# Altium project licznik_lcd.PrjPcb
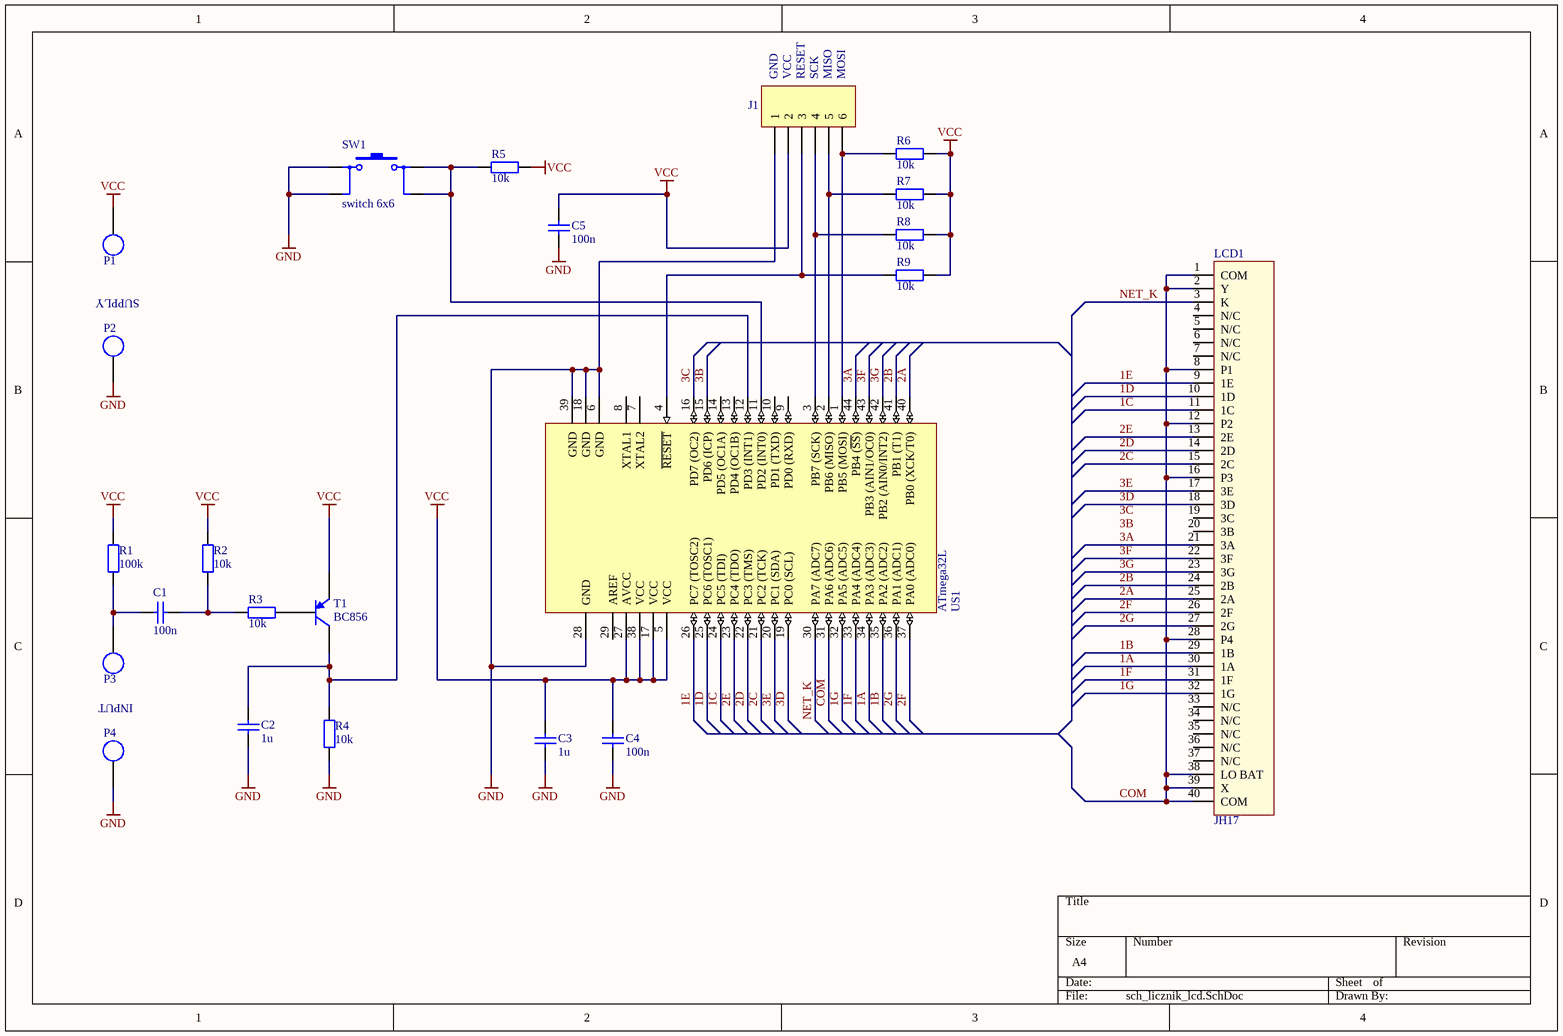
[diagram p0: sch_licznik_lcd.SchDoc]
1 sheet, 23 parts. Net scope: global (net labels, ports and power ports of the same name join across sheets).
Board file: pcb_licznik_lcd.PcbDoc

## Sheet sch_licznik_lcd.SchDoc
size A4

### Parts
C1  100n  [MELF-1206]
C2  1u  [MELF-1206]
C3  1u  [MELF-1206]
C4  100n  [MELF-1206]
C5  100n  [MELF-1206]
J1  (no value)  [HDR1X6H]
LCD1  JH17  [LCD JH17]
P1  WE  [pad fi 1mm]  (value not drawn)
P2  WE  [pad fi 1mm]  (value not drawn)
P3  WE  [pad fi 1mm]  (value not drawn)
P4  WE  [pad fi 1mm]  (value not drawn)
R1  100k  [MELF-1206]
R2  10k  [MELF-1206]
R3  10k  [MELF-1206]
R4  10k  [MELF-1206]
R5  10k  [MELF-1206]
R6  10k  [MELF-1206]
R7  10k  [MELF-1206]
R8  10k  [MELF-1206]
R9  10k  [MELF-1206]
SW1  switch 6x6  [tact switch 6x6]
T1  BC856  [318-08]
US1  ATmega32L  [44A_N]

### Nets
GND: C2.1 C3.1 C4.1 C5.1 J1.1 P2.1 P4.1 R4.1 SW1.1 SW1.3 US1.6(GND) US1.18(GND) US1.28(GND) US1.39(GND)
VCC: C3.2 C4.2 C5.2 J1.2 P1.1 R1.1 R2.1 R5.2 R6.1 R7.1 R8.1 R9.1 T1.2(E) US1.5(VCC) US1.17(VCC) US1.27(AVCC) US1.38(VCC)
1A: LCD1.30(1A) US1.34(PA3_(ADC3))
1B: LCD1.29(1B) US1.35(PA2_(ADC2))
1C: LCD1.11(1C) US1.24(PC5_(TDI))
1D: LCD1.10(1D) US1.25(PC6_(TOSC1))
1E: LCD1.9(1E) US1.26(PC7_(TOSC2))
1F: LCD1.31(1F) US1.33(PA4_(ADC4))
1G: LCD1.32(1G) US1.32(PA5_(ADC5))
2A: LCD1.25(2A) US1.40(PB0_(XCK/T0))
2B: LCD1.24(2B) US1.41(PB1_(T1))
2C: LCD1.15(2C) US1.21(PC2_(TCK))
2D: LCD1.14(2D) US1.22(PC3_(TMS))
2E: LCD1.13(2E) US1.23(PC4_(TDO))
2F: LCD1.26(2F) US1.37(PA0_(ADC0))
2G: LCD1.27(2G) US1.36(PA1_(ADC1))
3A: LCD1.21(3A) US1.44(PB4_(~{SS}))
3B: US1.15(PD6_(ICP))
3C: US1.16(PD7_(OC2))
3D: LCD1.18(3D) US1.19(PC0_(SCL))
3E: LCD1.17(3E) US1.20(PC1_(SDA))
3F: LCD1.22(3F) US1.43(PB3_(AIN1/OC0))
3G: LCD1.23(3G) US1.42(PB2_(AIN0/INT2))
COM: LCD1.1(COM) LCD1.2(Y) LCD1.8(P1) LCD1.12(P2) LCD1.16(P3) LCD1.28(P4) LCD1.38(LO_BAT) LCD1.39(X) LCD1.40(COM) US1.31(PA6_(ADC6))
NET_K: LCD1.3(K) US1.30(PA7_(ADC7))
NetC1_1: C1.1 P3.1 R1.2
NetC1_2: C1.2 R2.2 R3.1
NetC2_2: C2.2 R4.2 T1.3(C) US1.12(PD3_(INT1))
NetJ1_3: J1.3 R9.2 US1.4(~{RESET})
NetJ1_4: J1.4 R8.2 US1.3(PB7_(SCK))
NetJ1_5: J1.5 R7.2 US1.2(PB6_(MISO))
NetJ1_6: J1.6 R6.2 US1.1(PB5_(MOSI))
NetR3_2: R3.2 T1.1(B)
NetR5_1: R5.1 SW1.2 SW1.4 US1.11(PD2_(INT0))

Not connected (* = marked no-connect by the designer): LCD1 4(N/C) 5(N/C) 6(N/C) 7(N/C) 19(3C) 20(3B) 33(N/C) 34(N/C) 35(N/C) 36(N/C) 37(N/C); US1 7(XTAL2) 8(XTAL1) 9(PD0_(RXD)) 10(PD1_(TXD)) 13(PD4_(OC1B)) 14(PD5_(OC1A)) 29(AREF)

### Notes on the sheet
- (near J1) GND
- (near J1) VCC
- (near J1) RESET
- (near J1) SCK
- (near J1) MISO
- (near J1) MOSI
- SUPPLY
- INPUT
- Labels drawn without touching a wire or pin: 3B, 3C

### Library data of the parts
C1-C5 = kondensator
J1 = Header 6H: Header, 6-Pin, Right Angle
LCD1 = LCD JH17
P1-P4 = Pad
R1-R9 = rezystor
SW1 = switch
T1 = BC856ALT1: General Purpose Transistor PNP Silicon
US1 = ATmega32-16AC: 8-Bit AVR Microcontroller with 32K Bytes of In-System Programmable Flash Memory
